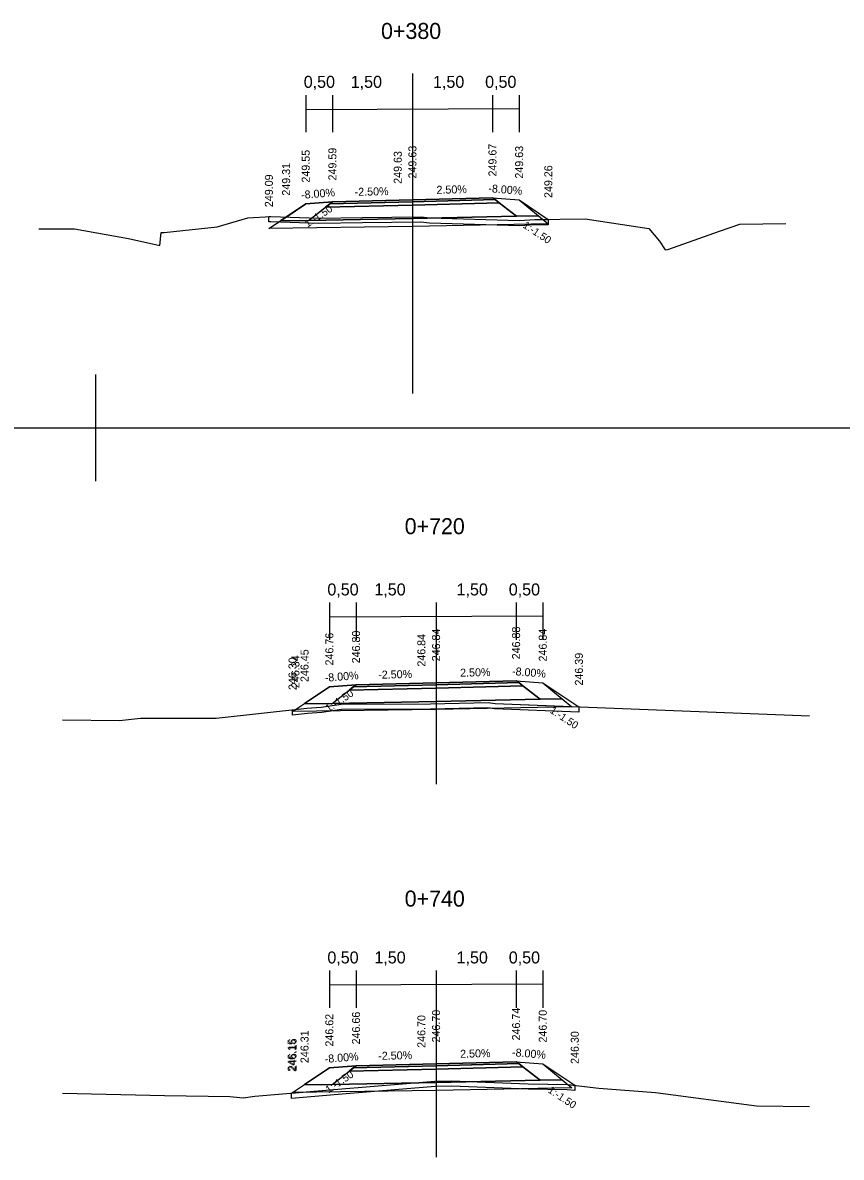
# Model space of a CAD drawing. Extents: x -552501 to -552394, y -1029983 to -1029892.
# Drawn here: x -552438.12 to -552422.78, y -1029936.72 to -1029915.46 of the extents above; entities that cross this region are included whole.
import ezdxf

# ---------------------------------------------------------------- set-up
doc = ezdxf.new("R2010")
doc.units = 0
for name, color, linetype in [('1', 7, 'Continuous'), ('16', 7, 'Continuous'), ('60', 7, 'Continuous'), ('9', 7, 'Continuous'), ('FORMATY', 7, 'Continuous'), ('Implicitní', 7, 'Continuous'), ('rámeček', 7, 'Continuous')]:
    doc.layers.add(name, color=color, linetype=linetype)

msp = doc.modelspace()

# ---------------------------------------------------------------- linework, layer by layer
for points in [[(-552433.505, -1029919.314), (-552433.182, -1029919.099), (-552432.815, -1029918.854), (-552432.315, -1029918.814), (-552430.815, -1029918.777), (-552429.315, -1029918.739), (-552428.815, -1029918.779), (-552428.268, -1029919.143)], [(-552437.815, -1029919.319), (-552437.15, -1029919.32), (-552436.139, -1029919.499), (-552435.551, -1029919.632), (-552435.523, -1029919.39), (-552435.468, -1029919.392), (-552434.472, -1029919.283), (-552433.899, -1029919.112), (-552433.469, -1029919.089), (-552432.57, -1029919.12), (-552431.752, -1029919.111), (-552430.654, -1029919.098), (-552430.491, -1029919.113), (-552428.806, -1029919.163), (-552428.523, -1029919.146), (-552427.579, -1029919.136), (-552426.385, -1029919.312), (-552426.186, -1029919.551), (-552426.075, -1029919.712), (-552426.025, -1029919.707), (-552425.06, -1029919.361), (-552424.676, -1029919.235), (-552423.815, -1029919.221)], [(-552433.062, -1029928.364), (-552433.008, -1029928.328), (-552432.837, -1029928.214), (-552432.372, -1029927.904), (-552431.872, -1029927.864), (-552430.372, -1029927.826), (-552428.872, -1029927.789), (-552428.372, -1029927.829), (-552427.695, -1029928.28)], [(-552437.372, -1029928.523), (-552436.307, -1029928.535), (-552435.909, -1029928.494), (-552434.493, -1029928.488), (-552432.791, -1029928.305), (-552432.526, -1029928.284), (-552432.15, -1029928.226), (-552430.476, -1029928.221), (-552429.397, -1029928.2), (-552429.266, -1029928.218), (-552423.372, -1029928.45)], [(-552433.079, -1029935.518), (-552433.062, -1029935.506), (-552432.837, -1029935.356), (-552432.372, -1029935.046), (-552431.872, -1029935.006), (-552430.372, -1029934.969), (-552428.872, -1029934.931), (-552428.372, -1029934.971), (-552427.772, -1029935.371)], [(-552437.372, -1029935.518), (-552435.463, -1029935.562), (-552434.235, -1029935.584), (-552433.985, -1029935.608), (-552433.766, -1029935.577), (-552432.215, -1029935.443), (-552430.394, -1029935.293), (-552430.085, -1029935.285), (-552428.643, -1029935.345), (-552427.906, -1029935.354), (-552427.322, -1029935.427), (-552426.26, -1029935.505), (-552424.367, -1029935.758), (-552423.372, -1029935.769)]]:
    msp.add_lwpolyline(points)
for points in [[(-552432.315, -1029918.814), (-552432.815, -1029918.854), (-552433.28, -1029919.164), (-552432.765, -1029919.164)], [(-552432.765, -1029919.164), (-552432.443, -1029918.914), (-552430.815, -1029918.877), (-552429.187, -1029918.833), (-552428.865, -1029919.083), (-552430.815, -1029919.127)], [(-552430.815, -1029918.817), (-552432.366, -1029918.854), (-552432.443, -1029918.914), (-552430.815, -1029918.877), (-552429.187, -1029918.833), (-552429.264, -1029918.773), (-552430.815, -1029918.817), (-552429.264, -1029918.773), (-552429.315, -1029918.739), (-552430.815, -1029918.777), (-552432.315, -1029918.814), (-552432.366, -1029918.854)], [(-552432.443, -1029918.914), (-552432.366, -1029918.854), (-552430.815, -1029918.817), (-552429.264, -1029918.773), (-552429.187, -1029918.833), (-552430.815, -1029918.877)], [(-552429.315, -1029918.739), (-552428.815, -1029918.779), (-552428.454, -1029919.077), (-552428.865, -1029919.083), (-552429.187, -1029918.833), (-552429.264, -1029918.773)], [(-552433.505, -1029919.314), (-552433.28, -1029919.164), (-552432.765, -1029919.164), (-552430.815, -1029919.127), (-552428.865, -1029919.083), (-552428.454, -1029919.077), (-552428.269, -1029919.227), (-552430.815, -1029919.277)], [(-552433.505, -1029919.091), (-552433.469, -1029919.089), (-552432.57, -1029919.12), (-552431.752, -1029919.111), (-552430.654, -1029919.098), (-552430.491, -1029919.113), (-552428.806, -1029919.163), (-552428.523, -1029919.146), (-552428.268, -1029919.143), (-552428.268, -1029919.243), (-552428.52, -1029919.246), (-552428.805, -1029919.263), (-552430.497, -1029919.213), (-552430.658, -1029919.198), (-552431.751, -1029919.211), (-552432.571, -1029919.22), (-552433.468, -1029919.189), (-552433.505, -1029919.191)], [(-552431.872, -1029927.864), (-552432.372, -1029927.904), (-552432.837, -1029928.214), (-552432.322, -1029928.214)], [(-552430.372, -1029927.866), (-552431.923, -1029927.904), (-552432, -1029927.964), (-552430.372, -1029927.926), (-552428.744, -1029927.883), (-552428.821, -1029927.823), (-552430.372, -1029927.866), (-552428.821, -1029927.823), (-552428.872, -1029927.789), (-552430.372, -1029927.826), (-552431.872, -1029927.864), (-552431.923, -1029927.904)], [(-552432, -1029927.964), (-552431.923, -1029927.904), (-552430.372, -1029927.866), (-552428.821, -1029927.823), (-552428.744, -1029927.883), (-552430.372, -1029927.926)], [(-552428.872, -1029927.789), (-552428.372, -1029927.829), (-552428.011, -1029928.126), (-552428.422, -1029928.133), (-552428.744, -1029927.883), (-552428.821, -1029927.823)], [(-552432.322, -1029928.214), (-552432, -1029927.964), (-552430.372, -1029927.926), (-552428.744, -1029927.883), (-552428.422, -1029928.133), (-552430.372, -1029928.176)], [(-552433.062, -1029928.364), (-552432.837, -1029928.214), (-552432.322, -1029928.214), (-552430.372, -1029928.176), (-552428.422, -1029928.133), (-552428.011, -1029928.126), (-552427.826, -1029928.276), (-552430.372, -1029928.326)], [(-552433.062, -1029928.334), (-552432.791, -1029928.305), (-552432.526, -1029928.284), (-552432.15, -1029928.226), (-552430.476, -1029928.221), (-552429.397, -1029928.2), (-552429.266, -1029928.218), (-552427.695, -1029928.28), (-552427.695, -1029928.38), (-552429.275, -1029928.318), (-552429.403, -1029928.3), (-552430.475, -1029928.321), (-552432.143, -1029928.326), (-552432.515, -1029928.384), (-552432.782, -1029928.404), (-552433.062, -1029928.434)], [(-552431.872, -1029935.006), (-552432.372, -1029935.046), (-552432.837, -1029935.356), (-552432.322, -1029935.356)], [(-552432.322, -1029935.356), (-552432, -1029935.106), (-552430.372, -1029935.069), (-552428.744, -1029935.025), (-552428.422, -1029935.275), (-552430.372, -1029935.319)], [(-552430.372, -1029935.009), (-552431.923, -1029935.046), (-552432, -1029935.106), (-552430.372, -1029935.069), (-552428.744, -1029935.025), (-552428.821, -1029934.965), (-552430.372, -1029935.009), (-552428.821, -1029934.965), (-552428.872, -1029934.931), (-552430.372, -1029934.969), (-552431.872, -1029935.006), (-552431.923, -1029935.046)], [(-552432, -1029935.106), (-552431.923, -1029935.046), (-552430.372, -1029935.009), (-552428.821, -1029934.965), (-552428.744, -1029935.025), (-552430.372, -1029935.069)], [(-552428.872, -1029934.931), (-552428.372, -1029934.971), (-552428.011, -1029935.269), (-552428.422, -1029935.275), (-552428.744, -1029935.025), (-552428.821, -1029934.965)], [(-552433.079, -1029935.518), (-552432.215, -1029935.443), (-552430.394, -1029935.293), (-552430.085, -1029935.285), (-552428.643, -1029935.345), (-552427.906, -1029935.354), (-552427.772, -1029935.371), (-552427.772, -1029935.471), (-552427.912, -1029935.454), (-552428.645, -1029935.445), (-552430.085, -1029935.385), (-552430.389, -1029935.393), (-552432.206, -1029935.543), (-552433.079, -1029935.618)], [(-552433.062, -1029935.506), (-552432.837, -1029935.356), (-552432.322, -1029935.356), (-552430.372, -1029935.319), (-552428.422, -1029935.275), (-552428.011, -1029935.269), (-552427.826, -1029935.419), (-552430.372, -1029935.469)]]:
    msp.add_lwpolyline(points, close=True)
at = {"layer": '60'}
for p, q in [((-552430.815, -1029916.408), (-552430.815, -1029922.408)), ((-552430.372, -1029926.667), (-552430.372, -1029929.727)), ((-552430.372, -1029933.667), (-552430.372, -1029936.721))]:
    msp.add_line(p, q, dxfattribs=at)
at = {"layer": '9'}
for p, q in [((-552432.815, -1029916.813), (-552432.815, -1029917.511)), ((-552432.315, -1029916.813), (-552432.315, -1029917.511)), ((-552430.815, -1029916.813), (-552430.815, -1029918.313)), ((-552429.315, -1029916.813), (-552429.315, -1029917.511)), ((-552428.815, -1029916.813), (-552428.815, -1029917.511)), ((-552432.372, -1029926.326), (-552432.372, -1029927.024)), ((-552431.872, -1029926.326), (-552431.872, -1029927.024)), ((-552430.372, -1029926.326), (-552430.372, -1029927.826)), ((-552428.872, -1029926.326), (-552428.872, -1029927.024)), ((-552428.372, -1029926.326), (-552428.372, -1029927.024)), ((-552432.372, -1029933.223), (-552432.372, -1029933.92)), ((-552431.872, -1029933.223), (-552431.872, -1029933.92)), ((-552430.372, -1029933.223), (-552430.372, -1029934.723)), ((-552428.872, -1029933.223), (-552428.872, -1029933.92)), ((-552428.372, -1029933.223), (-552428.372, -1029933.92))]:
    msp.add_line(p, q, dxfattribs=at)
at = {"layer": 'FORMATY'}
for p, q in [((-552436.755, -1029922.05), (-552436.755, -1029924.05)), ((-552437.755, -1029923.05), (-552435.755, -1029923.05))]:
    msp.add_line(p, q, dxfattribs=at)
at = {"layer": 'Implicitní'}
for p, q in [((-552432.805, -1029917.081), (-552428.815, -1029917.063)), ((-552432.362, -1029926.594), (-552428.372, -1029926.576)), ((-552432.362, -1029933.49), (-552428.372, -1029933.473))]:
    msp.add_line(p, q, dxfattribs=at)
at = {"layer": 'rámeček'}
for p, q in [((-552436.755, -1029922.55), (-552436.755, -1029923.05)), ((-552499.755, -1029923.05), (-552394.755, -1029923.05)), ((-552499.755, -1029923.05), (-552394.755, -1029923.05)), ((-552499.755, -1029923.05), (-552394.755, -1029923.05))]:
    msp.add_line(p, q, dxfattribs=at)

# ---------------------------------------------------------------- texts
for rotation, p in [(33.6902, (-552432.782, -1029919.301)), (326.3098, (-552428.758, -1029919.286)), (33.6902, (-552432.388, -1029928.383)), (326.3098, (-552428.25, -1029928.379)), (33.6901, (-552432.388, -1029935.526)), (326.3098, (-552428.288, -1029935.495))]:
    msp.add_text('1:-1.50', height=0.14, rotation=rotation).set_placement(p)
at = {"layer": '1'}
for s, p in [('0+380', (-552431.403, -1029915.762)), ('0+720', (-552430.96, -1029925.043)), ('0+740', (-552430.96, -1029932.023))]:
    msp.add_text(s, height=0.3, dxfattribs=at).set_placement(p)
at = {"layer": '16'}
for s, p in [('0,50', (-552432.852, -1029916.678)), ('1,50', (-552431.971, -1029916.678)), ('1,50', (-552430.429, -1029916.678)), ('0,50', (-552429.452, -1029916.678)), ('0,50', (-552432.409, -1029926.191)), ('1,50', (-552431.528, -1029926.191)), ('1,50', (-552429.987, -1029926.191)), ('0,50', (-552429.009, -1029926.191)), ('0,50', (-552432.409, -1029933.088)), ('1,50', (-552431.528, -1029933.088)), ('1,50', (-552429.987, -1029933.088)), ('0,50', (-552429.009, -1029933.088))]:
    msp.add_text(s, height=0.225, dxfattribs=at).set_placement(p)
for s, rotation, p in [('249.55', 90, (-552432.74, -1029918.454)), ('249.59', 90, (-552432.24, -1029918.414)), ('249.63', 90, (-552431.015, -1029918.477)), ('249.63', 90, (-552430.74, -1029918.377)), ('249.67', 90, (-552429.24, -1029918.339)), ('249.63', 90, (-552428.74, -1029918.379)), ('249.31', 90, (-552433.107, -1029918.699)), ('249.26', 90, (-552428.193, -1029918.743)), ('249.09', 90, (-552433.43, -1029918.914)), ('2.50%', 1.4321, (-552430.362, -1029918.665)), ('-8.00%', 355.4261, (-552429.396, -1029918.633)), ('-8.00%', 4.5739, (-552432.896, -1029918.76)), ('-2.50%', 1.4321, (-552431.896, -1029918.704)), ('246.88', 90, (-552428.797, -1029927.389)), ('246.76', 90, (-552432.297, -1029927.504)), ('246.80', 90, (-552431.797, -1029927.464)), ('246.84', 90, (-552430.572, -1029927.526)), ('246.84', 90, (-552430.297, -1029927.426)), ('246.84', 90, (-552428.297, -1029927.429)), ('246.45', 90, (-552432.762, -1029927.814)), ('246.30', 90, (-552432.987, -1029927.964)), ('246.34', 90, (-552432.933, -1029927.928)), ('246.39', 90, (-552427.62, -1029927.88)), ('-8.00%', 4.5739, (-552432.453, -1029927.81)), ('-2.50%', 1.4321, (-552431.454, -1029927.753)), ('2.50%', 1.4321, (-552429.919, -1029927.715)), ('-8.00%', 355.4261, (-552428.953, -1029927.682)), ('246.66', 90, (-552431.797, -1029934.606)), ('246.70', 90, (-552430.297, -1029934.569)), ('246.74', 90, (-552428.797, -1029934.531)), ('246.70', 90, (-552428.297, -1029934.571)), ('246.62', 90, (-552432.297, -1029934.646)), ('246.70', 90, (-552430.572, -1029934.669)), ('246.31', 90, (-552432.762, -1029934.956)), ('246.30', 90, (-552427.697, -1029934.971)), ('246.15', 90, (-552433.004, -1029935.118)), ('246.16', 90, (-552432.987, -1029935.106)), ('-8.00%', 4.5739, (-552432.453, -1029934.953)), ('-2.50%', 1.4321, (-552431.454, -1029934.896)), ('2.50%', 1.4321, (-552429.919, -1029934.857)), ('-8.00%', 355.4261, (-552428.953, -1029934.825))]:
    msp.add_text(s, height=0.15, rotation=rotation, dxfattribs=at).set_placement(p)

doc.saveas('drawing.dxf')
